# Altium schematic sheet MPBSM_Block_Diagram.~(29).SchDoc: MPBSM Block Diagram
size 431 x 279 mm; Date: Not shown in title block; ApprovedBy: Not shown in title block; CheckedBy: Not shown in title block; Author: Not shown in title block; CompanyName: Not shown in title block; DrawnBy: Ricky Zepeda; Engineer: Not shown in title block; Organization: Not shown in title block; Address1: Not shown in title block; Address2: Not shown in title block; Address3: Not shown in title block; Address4: Not shown in title block; DocumentNumber: 1; Revision: Use project parameter SCH_Rev; SheetNumber: 1; SheetTotal: 12; PageSetup: Record=PageOptions¦CenterHorizontal=True¦CenterVertical=True¦PrintScale=1.00¦XCorrection=1.00¦YCorrection=1.00¦PrintKind=0¦BorderSize=5000000¦LeftOffset=0¦BottomOffset=0¦Orientation=2¦PaperLength=1000¦PaperWidth=1000¦Scale=100¦PaperSource=15¦PrintQuality=600¦MediaType=1¦DitherType=10¦PaperKind=Letter¦PrintScaleMode=1
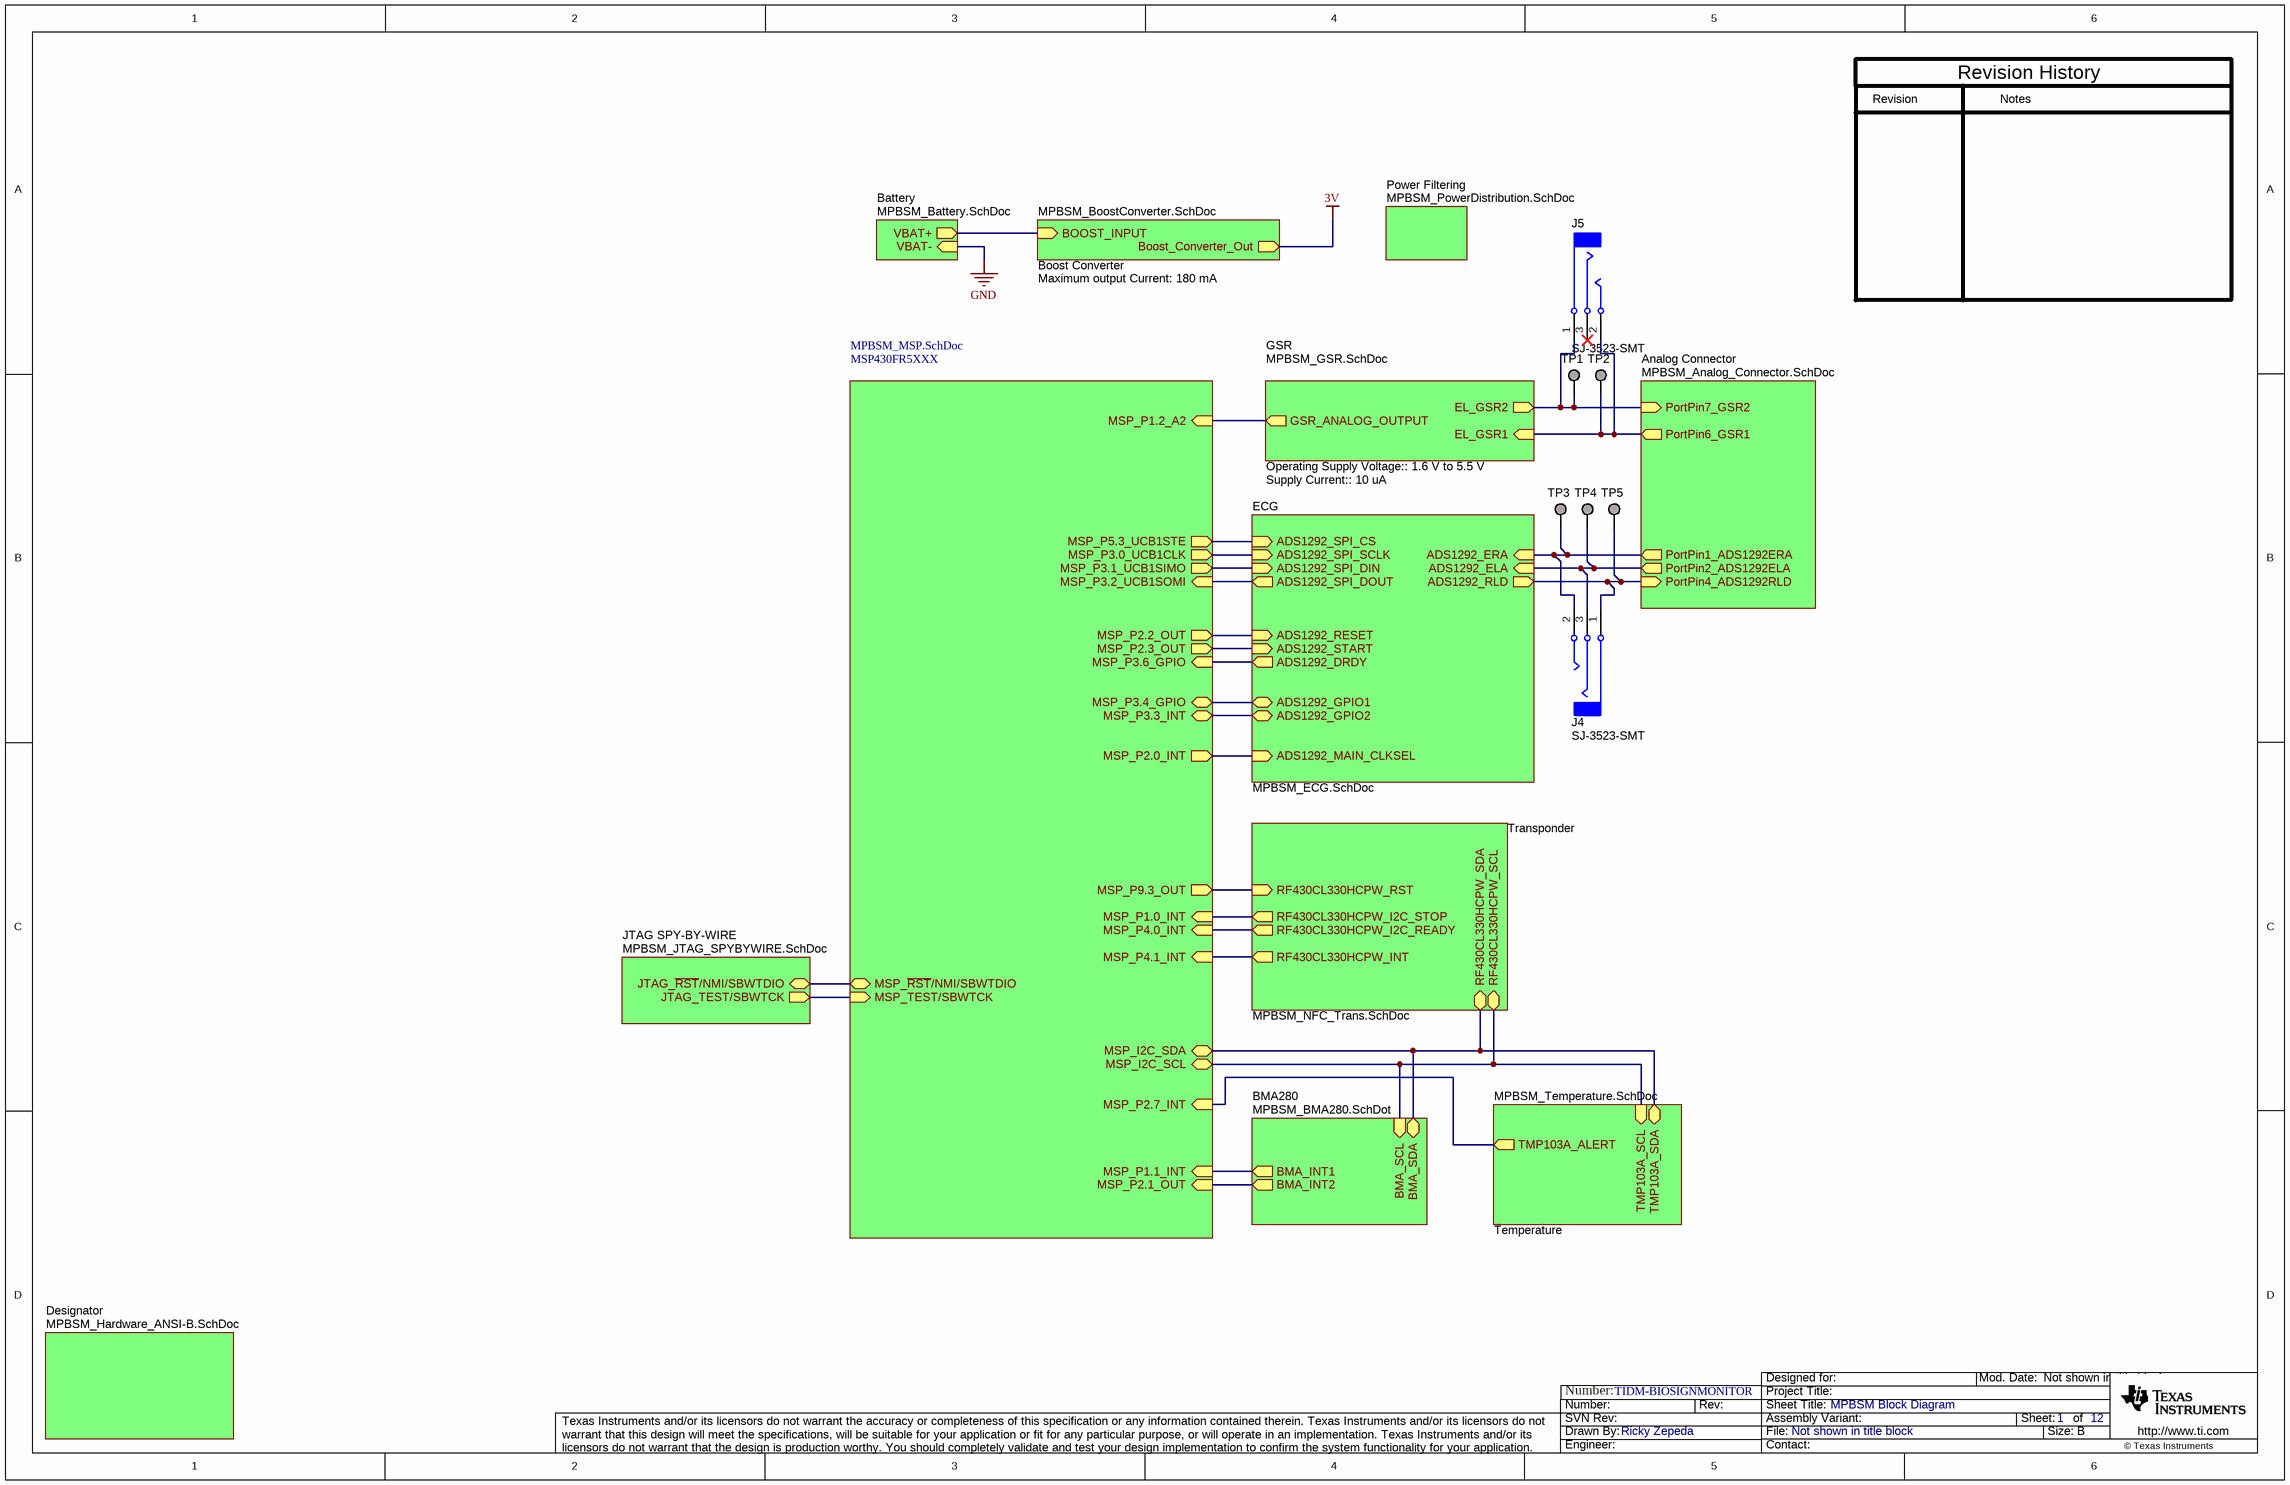
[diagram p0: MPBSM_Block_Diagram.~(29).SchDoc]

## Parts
J4  SJ-3523-SMT  [CUI_SJ-3523-SMT]
J5  SJ-3523-SMT  [CUI_SJ-3523-SMT]
TP1  TESTPOINT  [TP_SM_1MM]  (value not drawn)  (no BOM)
TP2  TESTPOINT  [TP_SM_1MM]  (value not drawn)  (no BOM)
TP3  TESTPOINT  [TP_SM_1MM]  (value not drawn)  (no BOM)
TP4  TESTPOINT  [TP_SM_1MM]  (value not drawn)  (no BOM)
TP5  TESTPOINT  [TP_SM_1MM]  (value not drawn)  (no BOM)

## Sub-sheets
Analog Connector = MPBSM_Analog_Connector.SchDoc: PortPin7_GSR2 (in), PortPin6_GSR1 (out), PortPin2_ADS1292ELA (out), PortPin4_ADS1292RLD (in), PortPin1_ADS1292ERA (out)
Battery = MPBSM_Battery.SchDoc: VBAT- (in), VBAT+ (out)
BMA280 = MPBSM_BMA280.SchDot: BMA_INT1 (out), BMA_INT2 (out), BMA_SDA (bidir), BMA_SCL (in)
Boost Converter = MPBSM_BoostConverter.SchDoc: BOOST_INPUT (in), Boost_Converter_Out (out)  | Maximum output Current: 180 mA
Designator = MPBSM_Hardware_ANSI-B.SchDoc: no entries
ECG = MPBSM_ECG.SchDoc: ADS1292_START (in), ADS1292_RESET (in), ADS1292_DRDY (out), ADS1292_SPI_CS (in), ADS1292_SPI_DIN (in), ADS1292_SPI_SCLK (in), ADS1292_SPI_DOUT (out), ADS1292_MAIN_CLKSEL (in), ADS1292_ERA (in), ADS1292_ELA (in), ADS1292_GPIO1 (bidir), ADS1292_GPIO2 (bidir), ADS1292_RLD (out)
GSR = MPBSM_GSR.SchDoc: GSR_ANALOG_OUTPUT (out), EL_GSR2 (out), EL_GSR1 (in)  | Operating Supply Voltage:: 1.6 V to 5.5 V; Supply Current:: 10 uA
JTAG SPY-BY-WIRE = MPBSM_JTAG_SPYBYWIRE.SchDoc: JTAG_~{RST}/NMI/SBWTDIO (bidir), JTAG_TEST/SBWTCK (out)
MSP430FR5XXX = MPBSM_MSP.SchDoc: MSP_TEST/SBWTCK (in), MSP_~{RST}/NMI/SBWTDIO (bidir), MSP_I2C_SDA (bidir), MSP_I2C_SCL (bidir), MSP_P1.2_A2 (in), MSP_P2.0_INT (out), MSP_P4.0_INT (in), MSP_P4.1_INT (in), MSP_P2.7_INT (in), MSP_P9.3_OUT (out), MSP_P2.2_OUT (out), MSP_P2.3_OUT (out), MSP_P1.0_INT (in), MSP_P2.1_OUT (in), MSP_P3.0_UCB1CLK (out), MSP_P3.3_INT (bidir), MSP_P3.2_UCB1SOMI (in), MSP_P3.4_GPIO (bidir), MSP_P3.6_GPIO (in), MSP_P1.1_INT (in), MSP_P5.3_UCB1STE (out), MSP_P3.1_UCB1SIMO (out)
Power Filtering = MPBSM_PowerDistribution.SchDoc: no entries
Temperature = MPBSM_Temperature.SchDoc: TMP103A_SCL (in), TMP103A_SDA (bidir), TMP103A_ALERT (out)
Transponder = MPBSM_NFC_Trans.SchDoc: RF430CL330HCPW_RST (in), RF430CL330HCPW_SCL (bidir), RF430CL330HCPW_SDA (bidir), RF430CL330HCPW_I2C_STOP (out), RF430CL330HCPW_I2C_READY (out), RF430CL330HCPW_INT (out)

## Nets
NetJ4_1: J4.1(SLEEVE) TP5.1 ; sheet ECG/ADS1292_RLD, sheet Analog Connector/PortPin4_ADS1292RLD
NetJ4_2: J4.2(TIP) TP3.1 ; sheet ECG/ADS1292_ERA, sheet Analog Connector/PortPin1_ADS1292ERA
NetJ4_3: J4.3(RING) TP4.1 ; sheet ECG/ADS1292_ELA, sheet Analog Connector/PortPin2_ADS1292ELA
NetJ5_1: J5.1(SLEEVE) TP1.1 ; sheet GSR/EL_GSR2, sheet Analog Connector/PortPin7_GSR2
NetJ5_2: J5.2(TIP) TP2.1 ; sheet GSR/EL_GSR1, sheet Analog Connector/PortPin6_GSR1
(unnamed): sheet MSP430FR5XXX/MSP_TEST/SBWTCK, sheet JTAG SPY-BY-WIRE/JTAG_TEST/SBWTCK
(unnamed): sheet MSP430FR5XXX/MSP_~{RST}/NMI/SBWTDIO, sheet JTAG SPY-BY-WIRE/JTAG_~{RST}/NMI/SBWTDIO  [a separate net that carries the same name]
(unnamed): sheet MSP430FR5XXX/MSP_I2C_SDA, sheet Transponder/RF430CL330HCPW_SDA, sheet BMA280/BMA_SDA, sheet Temperature/TMP103A_SDA  [a separate net that carries the same name]
(unnamed): sheet MSP430FR5XXX/MSP_I2C_SCL, sheet Transponder/RF430CL330HCPW_SCL, sheet BMA280/BMA_SCL, sheet Temperature/TMP103A_SCL  [a separate net that carries the same name]
(unnamed): sheet MSP430FR5XXX/MSP_P1.2_A2, sheet GSR/GSR_ANALOG_OUTPUT  [a separate net that carries the same name]
(unnamed): sheet MSP430FR5XXX/MSP_P2.0_INT, sheet ECG/ADS1292_MAIN_CLKSEL  [a separate net that carries the same name]
(unnamed): sheet MSP430FR5XXX/MSP_P4.0_INT, sheet Transponder/RF430CL330HCPW_I2C_READY  [a separate net that carries the same name]
(unnamed): sheet MSP430FR5XXX/MSP_P4.1_INT, sheet Transponder/RF430CL330HCPW_INT  [a separate net that carries the same name]
(unnamed): sheet MSP430FR5XXX/MSP_P2.7_INT, sheet Temperature/TMP103A_ALERT  [a separate net that carries the same name]
(unnamed): sheet MSP430FR5XXX/MSP_P9.3_OUT, sheet Transponder/RF430CL330HCPW_RST  [a separate net that carries the same name]
(unnamed): sheet MSP430FR5XXX/MSP_P2.2_OUT, sheet ECG/ADS1292_RESET  [a separate net that carries the same name]
(unnamed): sheet MSP430FR5XXX/MSP_P2.3_OUT, sheet ECG/ADS1292_START  [a separate net that carries the same name]
(unnamed): sheet MSP430FR5XXX/MSP_P1.0_INT, sheet Transponder/RF430CL330HCPW_I2C_STOP  [a separate net that carries the same name]
(unnamed): sheet MSP430FR5XXX/MSP_P2.1_OUT, sheet BMA280/BMA_INT2  [a separate net that carries the same name]
(unnamed): sheet MSP430FR5XXX/MSP_P3.0_UCB1CLK, sheet ECG/ADS1292_SPI_SCLK  [a separate net that carries the same name]
(unnamed): sheet MSP430FR5XXX/MSP_P3.3_INT, sheet ECG/ADS1292_GPIO2  [a separate net that carries the same name]
(unnamed): sheet MSP430FR5XXX/MSP_P3.2_UCB1SOMI, sheet ECG/ADS1292_SPI_DOUT  [a separate net that carries the same name]
(unnamed): sheet MSP430FR5XXX/MSP_P3.4_GPIO, sheet ECG/ADS1292_GPIO1  [a separate net that carries the same name]
(unnamed): sheet MSP430FR5XXX/MSP_P3.6_GPIO, sheet ECG/ADS1292_DRDY  [a separate net that carries the same name]
(unnamed): sheet MSP430FR5XXX/MSP_P1.1_INT, sheet BMA280/BMA_INT1  [a separate net that carries the same name]
(unnamed): sheet MSP430FR5XXX/MSP_P5.3_UCB1STE, sheet ECG/ADS1292_SPI_CS  [a separate net that carries the same name]
(unnamed): sheet MSP430FR5XXX/MSP_P3.1_UCB1SIMO, sheet ECG/ADS1292_SPI_DIN  [a separate net that carries the same name]
(unnamed): sheet Battery/VBAT+, sheet Boost Converter/BOOST_INPUT  [a separate net that carries the same name]

Not connected (* = marked no-connect by the designer): J5 3(RING)*

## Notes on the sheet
- Revision
- Notes
- Revision History
- Number:
- TIDM-BIOSIGNMONITOR

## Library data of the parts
J4 J5 = SJ-3523-SMT: Audio Jack, 3.5mm, Stereo, R/A, SMT; Manufacturer: CUI Inc.; SymbolCreator: a0412235
TP1-TP5 = TP_SM_1MM: 1mm Test Point, SMT; Manufacturer: Any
